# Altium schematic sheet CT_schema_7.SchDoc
size 274 x 160 mm
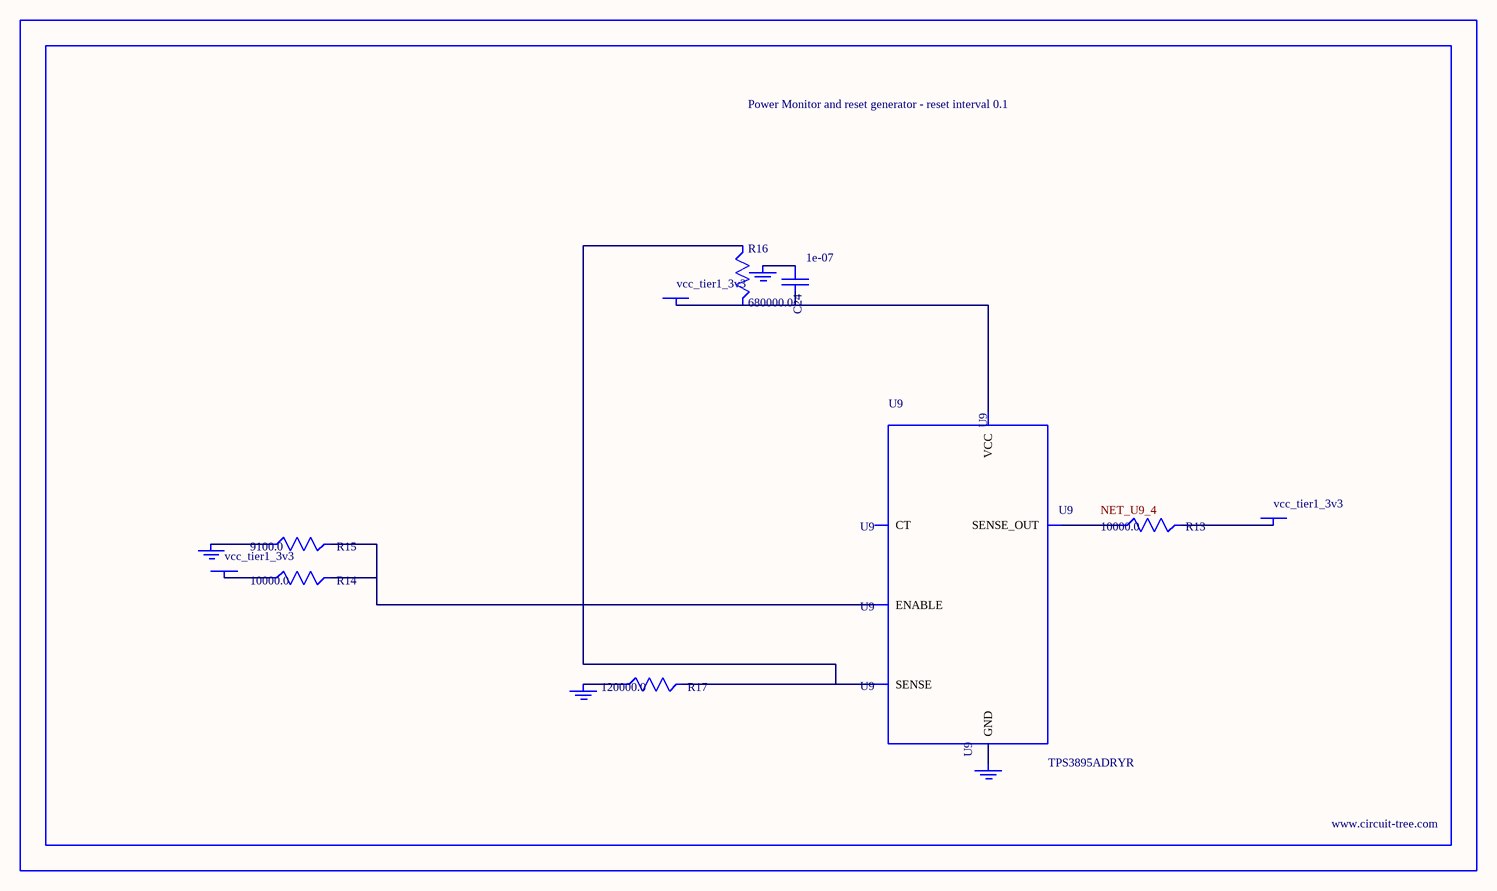
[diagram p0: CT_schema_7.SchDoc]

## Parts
BORDER6  (no value)
C24  1e-07  [C0402]
GND_INSTANCE_6_0  (no value)
GND_INSTANCE_6_1  (no value)
GND_INSTANCE_6_2  (no value)
GND_INSTANCE_6_3  (no value)
POWER_INSTANCE_6_0  vcc_tier1_3v3
POWER_INSTANCE_6_1  vcc_tier1_3v3
POWER_INSTANCE_6_2  vcc_tier1_3v3
R13  10000.0  [R0603]
R14  10000.0  [R0603]
R15  9100.0  [R0603]
R16  680000.0  [R0603]
R17  120000.0  [R0603]
U9  TPS3895ADRYR  [SON-6]

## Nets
NetC24_1: C24.1 GND_INSTANCE_6_2.0(GND)
NetC24_2: C24.2 POWER_INSTANCE_6_2.0(PWR) R16.2 U9.6(VCC)
NetGND_INSTANCE_6_0_0: GND_INSTANCE_6_0.0(GND) R15.1
NetGND_INSTANCE_6_1_0: GND_INSTANCE_6_1.0(GND) R17.1
NetGND_INSTANCE_6_3_0: GND_INSTANCE_6_3.0(GND) U9.2(GND)
NetPOWER_INSTANCE_6_0_0: POWER_INSTANCE_6_0.0(PWR) R14.1
NetPOWER_INSTANCE_6_1_0: POWER_INSTANCE_6_1.0(PWR) R13.2
NetR13_1: R13.1 U9.4(SENSE_OUT)
NetR14_2: R14.2 R15.2 U9.1(ENABLE)
NetR16_1: R16.1 R17.2 U9.3(SENSE)

Not connected (* = marked no-connect by the designer): U9 5(CT)

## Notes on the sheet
- Labels drawn without touching a wire or pin: NET_U9_4

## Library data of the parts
BORDER6 = BORDER_PAGE6
C24 = C0402C104K3RACTU
GND_INSTANCE_6_0-GND_INSTANCE_6_3 = GND
POWER_INSTANCE_6_0-POWER_INSTANCE_6_2 = PWR
R13 R14 = RC0603JR-0710KL
R15 = RC0603JR-079K1L
R16 = RC0603JR-07680KL
R17 = RC0603JR-07120KL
